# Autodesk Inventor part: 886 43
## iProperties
Created: 2005-11
Part Number: 886 43
Material: 1.4301 X5CrNi10-10 A2
Description: Flansch DN200 ISO-K
Document SubType Name: Modellieren
Designer: Mittelmeyer
Manufacturer: Standard
Standards Organization: Custom
Author: Mittelmeyer
Comments: LEYBOLD
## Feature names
1. Extrusion2
2. Extrusion3
3. Extrusion4
4. Drehung1 [Revolution]
5. Bohrung1 [Hole]
